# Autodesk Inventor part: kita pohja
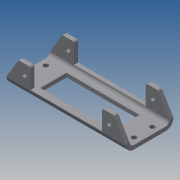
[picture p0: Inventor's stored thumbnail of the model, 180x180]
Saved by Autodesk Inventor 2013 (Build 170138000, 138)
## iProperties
Created: 2013-08
Part Number: kita pohja
Material: Generic
Document SubType Name: Sheet Metal
Designer: Reko Tuppurainen
Density: 1 g/cm^3
Sheet Metal Rule: Default_mm
Author: Reko Tuppurainen
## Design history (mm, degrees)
node "Face1"
  sketch "Sketch1"
    geometry: L1 (-150, 60)-(150, 60); L2 (150, 60)-(150, -60); L3 (150, -60)-(-150, -60); L4 (-150, -60)-(-150, 60); 2 further points
    constraints: 8 end point, 2 parallel, 1 coincident, 1 horizontal, 1 perpendicular
    dimensions: "d0" = 300 distance of L2.end L3.end; "d1" = 120 distance of L1.end L2.end
node "Flange1"
node "Flange2"
sketch "Sketch4"
  geometry: L1 (300, 50)-(0, 50) reference; L2 (0, 0)-(0, 50) reference; L3 (300, 0)-(0, 0) reference; L4 (300, 50)-(300, 0) reference; L5 (60, 0)-(60, 50); L6 (240, 0)-(240, 50); 1 further point
  constraints: 4 end point, 4 point on line, 1 parallel, 1 perpendicular
  dimensions: "d23" = 60 distance between parallel lines of L2 L5; "d24" = 60 distance between parallel lines of L4 L6
cut "Cut1" sketch "Sketch4" dims "d25" = 10 (= Thickness), "d26" = 0
sketch "Sketch5"
  geometry: C1 r 6 at (43.672, 25); 1 further point
  constraints: 1 centre point
  dimensions: "d27" = 12 diameter of C1
cut "Cut2" sketch "Sketch5" dims "d28" = 10 (= Thickness), "d29" = 0
sketch "Sketch6"
  geometry: L1 (0, 50)-(0, 0) reference; C1 r 6 at (-43.672, 25); 1 further point
  constraints: 1 centre point
  dimensions: "d30" = 12 diameter of C1; "d31" = 43.672 distance from line of L1 C1.centre
cut "Cut3" sketch "Sketch6" dims "d32" = 10 (= Thickness), "d33" = 0
sketch "Sketch7"
  geometry: L1 (0, 0)-(0, 50) reference; L2 (60, 0)-(0, 0) reference; L3 (0, 50)-(30, 0); 1 further point
  constraints: 2 end point, 1 midpoint
cut "Cut4" sketch "Sketch7" dims "d34" = 10 (= Thickness), "d35" = 0
feature "Corner Round1" dims "d36" = 6
sketch "Sketch8"
  geometry: L1 (0, 0)-(-60, 0) reference; L2 (0, 50)-(0, 0) reference; L3 (0, 50)-(-30, 0); 1 further point
  constraints: 2 end point, 1 midpoint
  dimensions: "d37" = 30 distance of L3.end L1.start
cut "Cut5" sketch "Sketch8" dims "d38" = 10 (= Thickness), "d39" = 0
feature "Corner Round2" dims "d40" = 6
sketch "Sketch9"
  geometry: L1 (-150, -40)-(150, -40) reference; L2 (150, 40)-(150, -40) reference; L3 (150, 40)-(-150, 40) reference; L4 (-150, -40)-(-150, 40) reference; L5 (-92, 33)-(92, 33); L6 (92, 33)-(92, -33); L7 (92, -33)-(-92, -33); L8 (-92, -33)-(-92, 33); C1 r 6 at (-134, 23); C2 r 6 at (-134, -23); C3 r 6 at (134, 23); C4 r 6 at (134, -23); 1 further point
  constraints: 8 end point, 4 centre point, 2 parallel, 1 horizontal, 1 perpendicular
  dimensions: "d41" = 58 distance between parallel lines of L4 L8; "d42" = 58 distance between parallel lines of L6 L2; "d43" = 7 distance between parallel lines of L5 L3; "d44" = 7 distance between parallel lines of L7 L1; "d45" = 12 diameter of C1; "d46" = 12 diameter of C2; "d47" = 12 diameter of C3; "d48" = 12 diameter of C4; "d49" = 16 distance from line of L4 C1.centre; "d50" = 17 distance from line of L3 C1.centre; "d51" = 16 distance from line of L4 C2.centre; "d52" = 17 distance from line of L1 C2.centre; "d53" = 16 distance from line of L2 C4.centre; "d54" = 17 distance from line of L1 C4.centre; "d55" = 16 distance from line of L2 C3.centre; "d56" = 17 distance from line of L3 C3.centre
cut "Cut6" sketch "Sketch9" dims "d57" = 10 (= Thickness), "d58" = 0
body "Solid1"
face "Plate1" dims "Thickness" = 10 (derived)
sketch "Sketch2"
  geometry: L1 through (-150, 0) direction (1, 0); L2 through (0, 35) direction (0, 1); L3 (0, 70)-(-300, 70); L4 (-300, 70)-(-300, 0)
  constraints: 6 end point, 1 horizontal, 1 perpendicular, 1 vertical
face "Plate2" dims "d3" = 10 (= BendReliefWidth), "d4" = 5 (= BendReliefDepth), "d5" = 20 (= MinimumRemnant), "d6" = 10 (= BendRadius), "d7" = 70, "d8" = 90 deg, "d9" = 10 (= BendRadius), "d10" = 40 (= CornerReliefSize), "d11" = 10 (= GapSize), "d12" = 10 (= JacobiRadiusSize), "SeamGap" = 0.01, "Thickness" = 10 (derived)
bend "Bend1" dims "d3" = 10 (= BendReliefWidth), "d4" = 5 (= BendReliefDepth), "d5" = 20 (= MinimumRemnant), "d6" = 10 (= BendRadius), "d7" = 70, "d8" = 90 deg, "d9" = 10 (= BendRadius), "SeamGap" = 0.01, "Thickness" = 10 (derived)
feature "Corner1" dims "d7" = 70, "d8" = 90 deg, "d10" = 40 (= CornerReliefSize), "d11" = 10 (= GapSize), "d12" = 10 (= JacobiRadiusSize)
sketch "Sketch3"
  geometry: L1 through (-150, 0) direction (1, 0); L2 through (0, 35) direction (0, 1); L3 (0, 70)-(-300, 70); L4 (-300, 70)-(-300, 0)
  constraints: 6 end point, 1 horizontal, 1 perpendicular, 1 vertical
face "Plate3" dims "d13" = 10 (= BendReliefWidth), "d14" = 5 (= BendReliefDepth), "d15" = 20 (= MinimumRemnant), "d16" = 10 (= BendRadius), "d17" = 70, "d18" = 90 deg, "d19" = 10 (= BendRadius), "d20" = 40 (= CornerReliefSize), "d21" = 10 (= GapSize), "d22" = 10 (= JacobiRadiusSize), "SeamGap" = 0.01, "Thickness" = 10 (derived)
bend "Bend2" dims "d13" = 10 (= BendReliefWidth), "d14" = 5 (= BendReliefDepth), "d15" = 20 (= MinimumRemnant), "d16" = 10 (= BendRadius), "d17" = 70, "d18" = 90 deg, "d19" = 10 (= BendRadius), "SeamGap" = 0.01, "Thickness" = 10 (derived)
feature "Corner2" dims "d17" = 70, "d18" = 90 deg, "d20" = 40 (= CornerReliefSize), "d21" = 10 (= GapSize), "d22" = 10 (= JacobiRadiusSize)
other parameters: "BendRadius" = 10 (= Thickness), "BendReliefDepth" = 5 (= 0.5 x Thickness)
